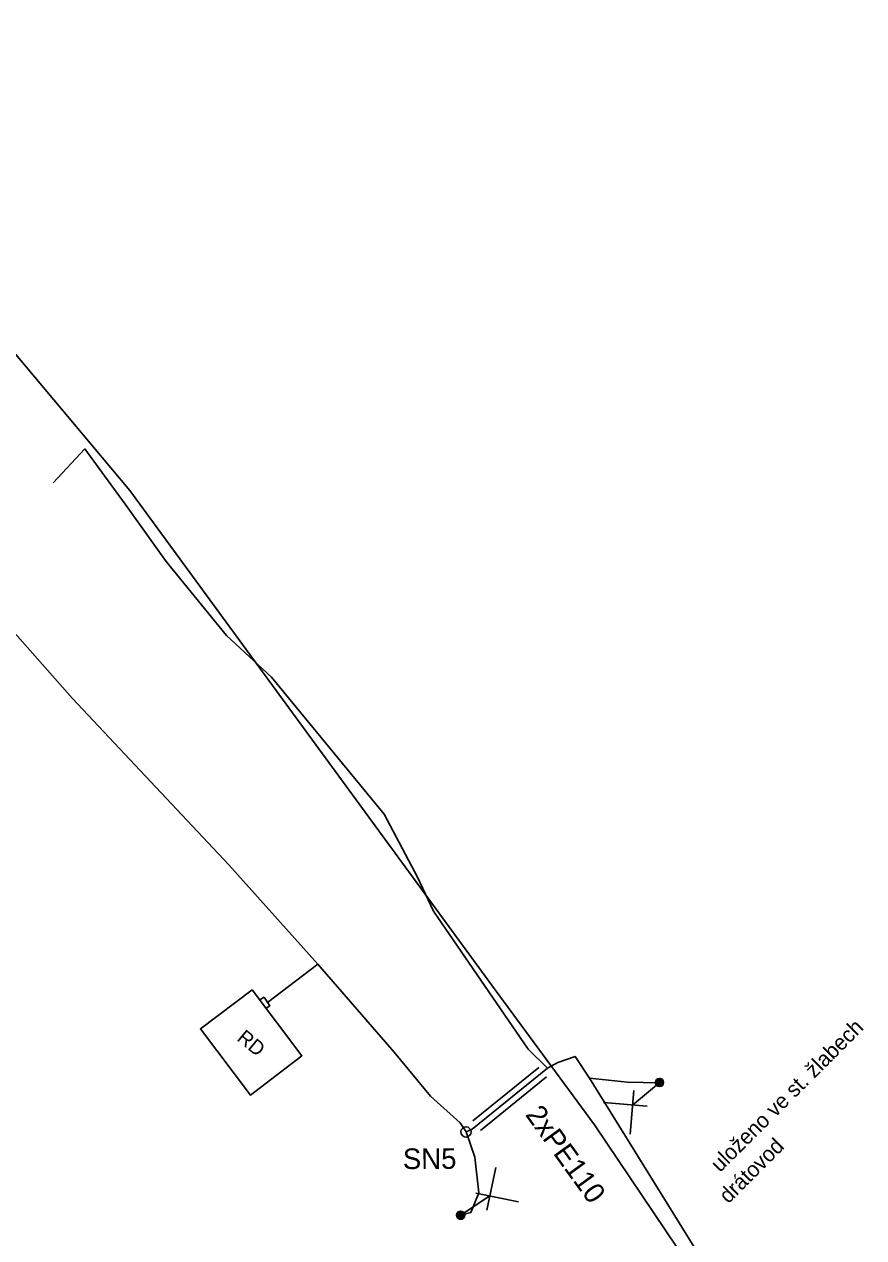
# Model space of a CAD drawing. Extents: x -731967 to -723173, y -945358 to -941505.
# Drawn here: x -725876.3 to -725835.6, y -942340.7 to -942281.8 of the extents above; entities that cross this region are included whole.
import ezdxf

# ---------------------------------------------------------------- set-up
doc = ezdxf.new("R2010")
doc.units = 0
for name, color, linetype in [('Vrstva 2', 7, 'Continuous'), ('Vrstva 28', 7, 'Continuous'), ('Vrstva 35', 7, 'Continuous')]:
    doc.layers.add(name, color=color, linetype=linetype)

msp = doc.modelspace()

# ---------------------------------------------------------------- linework, layer by layer
at = {"layer": 'Vrstva 2'}
for p, q in [((-725845.654, -942333.308), (-725846.804, -942334.272)), ((-725845.654, -942333.308), (-725846.804, -942334.272)), ((-725846.741, -942333.568), (-725846.928, -942335.682)), ((-725846.741, -942333.568), (-725846.928, -942335.682)), ((-725846.101, -942334.334), (-725848.213, -942334.147)), ((-725846.101, -942334.334), (-725848.213, -942334.147)), ((-725853.873, -942339.378), (-725853.443, -942337.3)), ((-725853.873, -942339.378), (-725853.443, -942337.3)), ((-725854.421, -942338.544), (-725852.344, -942338.974)), ((-725854.421, -942338.544), (-725852.344, -942338.974)), ((-725854.983, -942339.51), (-725853.728, -942338.686)), ((-725854.983, -942339.51), (-725853.728, -942338.686))]:
    msp.add_line(p, q, dxfattribs=at)
for points in [[(-725865.27, -942328.68), (-725862.85, -942331.88), (-725865.35, -942333.79), (-725867.779, -942330.578), (-725865.27, -942328.68)], [(-725865.27, -942328.68), (-725862.85, -942331.88), (-725865.35, -942333.79), (-725867.779, -942330.578), (-725865.27, -942328.68)], [(-725864.69, -942329.03), (-725864.901, -942329.168)], [(-725864.69, -942329.03), (-725864.901, -942329.168)], [(-725864.69, -942329.03), (-725864.41, -942329.46), (-725864.591, -942329.578)], [(-725864.69, -942329.03), (-725864.41, -942329.46), (-725864.591, -942329.578)], [(-725851.362, -942332.444), (-725854.56, -942335.039)], [(-725851.362, -942332.444), (-725854.56, -942335.039)], [(-725850.984, -942332.91), (-725854.182, -942335.505)], [(-725850.984, -942332.91), (-725854.182, -942335.505)], [(-725845.373, -942333.334), (-725845.315, -942333.243), (-725845.317, -942333.123), (-725845.384, -942333.029), (-725845.475, -942332.992), (-725845.585, -942333.01), (-725845.669, -942333.091), (-725845.692, -942333.19), (-725845.659, -942333.285), (-725845.57, -942333.354), (-725845.462, -942333.359), (-725845.382, -942333.315), (-725845.33, -942333.224), (-725845.34, -942333.115), (-725845.401, -942333.041), (-725845.488, -942333.011), (-725845.59, -942333.034), (-725845.657, -942333.109), (-725845.671, -942333.194), (-725845.635, -942333.284), (-725845.551, -942333.34), (-725845.46, -942333.339), (-725845.389, -942333.294), (-725845.347, -942333.207), (-725845.362, -942333.114), (-725845.416, -942333.056), (-725845.5, -942333.03), (-725845.59, -942333.058), (-725845.641, -942333.123), (-725845.651, -942333.201), (-725845.612, -942333.28), (-725845.537, -942333.323), (-725845.463, -942333.319), (-725845.396, -942333.274), (-725845.365, -942333.193), (-725845.381, -942333.118), (-725845.432, -942333.068), (-725845.512, -942333.05), (-725845.586, -942333.079), (-725845.624, -942333.134), (-725845.63, -942333.207), (-725845.591, -942333.275), (-725845.527, -942333.304), (-725845.464, -942333.298), (-725845.406, -942333.253), (-725845.385, -942333.184), (-725845.401, -942333.125), (-725845.45, -942333.08), (-725845.52, -942333.07), (-725845.577, -942333.098), (-725845.608, -942333.146), (-725845.608, -942333.212), (-725845.573, -942333.264), (-725845.522, -942333.286), (-725845.463, -942333.278), (-725845.417, -942333.235), (-725845.404, -942333.18), (-725845.419, -942333.131), (-725845.465, -942333.094), (-725845.523, -942333.09), (-725845.566, -942333.113), (-725845.591, -942333.158), (-725845.587, -942333.214), (-725845.557, -942333.252), (-725845.515, -942333.267), (-725845.465, -942333.256), (-725845.431, -942333.22), (-725845.424, -942333.178), (-725845.44, -942333.136), (-725845.479, -942333.11), (-725845.522, -942333.11), (-725845.553, -942333.129), (-725845.574, -942333.168), (-725845.567, -942333.21), (-725845.544, -942333.236), (-725845.507, -942333.248), (-725845.47, -942333.237), (-725845.448, -942333.208), (-725845.444, -942333.176), (-725845.46, -942333.145), (-725845.49, -942333.127), (-725845.519, -942333.13), (-725845.543, -942333.147), (-725845.555, -942333.176), (-725845.548, -942333.205), (-725845.53, -942333.222), (-725845.503, -942333.228), (-725845.477, -942333.218), (-725845.465, -942333.199), (-725845.464, -942333.177), (-725845.476, -942333.155), (-725845.496, -942333.145), (-725845.515, -942333.148), (-725845.53, -942333.161), (-725845.536, -942333.181), (-725845.529, -942333.196), (-725845.518, -942333.207), (-725845.501, -942333.209), (-725845.489, -942333.202), (-725845.482, -942333.191), (-725845.483, -942333.177)], [(-725845.373, -942333.334), (-725845.315, -942333.243), (-725845.317, -942333.123), (-725845.384, -942333.029), (-725845.475, -942332.992), (-725845.585, -942333.01), (-725845.669, -942333.091), (-725845.692, -942333.19), (-725845.659, -942333.285), (-725845.57, -942333.354), (-725845.462, -942333.359), (-725845.382, -942333.315), (-725845.33, -942333.224), (-725845.34, -942333.115), (-725845.401, -942333.041), (-725845.488, -942333.011), (-725845.59, -942333.034), (-725845.657, -942333.109), (-725845.671, -942333.194), (-725845.635, -942333.284), (-725845.551, -942333.34), (-725845.46, -942333.339), (-725845.389, -942333.294), (-725845.347, -942333.207), (-725845.362, -942333.114), (-725845.416, -942333.056), (-725845.5, -942333.03), (-725845.59, -942333.058), (-725845.641, -942333.123), (-725845.651, -942333.201), (-725845.612, -942333.28), (-725845.537, -942333.323), (-725845.463, -942333.319), (-725845.396, -942333.274), (-725845.365, -942333.193), (-725845.381, -942333.118), (-725845.432, -942333.068), (-725845.512, -942333.05), (-725845.586, -942333.079), (-725845.624, -942333.134), (-725845.63, -942333.207), (-725845.591, -942333.275), (-725845.527, -942333.304), (-725845.464, -942333.298), (-725845.406, -942333.253), (-725845.385, -942333.184), (-725845.401, -942333.125), (-725845.45, -942333.08), (-725845.52, -942333.07), (-725845.577, -942333.098), (-725845.608, -942333.146), (-725845.608, -942333.212), (-725845.573, -942333.264), (-725845.522, -942333.286), (-725845.463, -942333.278), (-725845.417, -942333.235), (-725845.404, -942333.18), (-725845.419, -942333.131), (-725845.465, -942333.094), (-725845.523, -942333.09), (-725845.566, -942333.113), (-725845.591, -942333.158), (-725845.587, -942333.214), (-725845.557, -942333.252), (-725845.515, -942333.267), (-725845.465, -942333.256), (-725845.431, -942333.22), (-725845.424, -942333.178), (-725845.44, -942333.136), (-725845.479, -942333.11), (-725845.522, -942333.11), (-725845.553, -942333.129), (-725845.574, -942333.168), (-725845.567, -942333.21), (-725845.544, -942333.236), (-725845.507, -942333.248), (-725845.47, -942333.237), (-725845.448, -942333.208), (-725845.444, -942333.176), (-725845.46, -942333.145), (-725845.49, -942333.127), (-725845.519, -942333.13), (-725845.543, -942333.147), (-725845.555, -942333.176), (-725845.548, -942333.205), (-725845.53, -942333.222), (-725845.503, -942333.228), (-725845.477, -942333.218), (-725845.465, -942333.199), (-725845.464, -942333.177), (-725845.476, -942333.155), (-725845.496, -942333.145), (-725845.515, -942333.148), (-725845.53, -942333.161), (-725845.536, -942333.181), (-725845.529, -942333.196), (-725845.518, -942333.207), (-725845.501, -942333.209), (-725845.489, -942333.202), (-725845.482, -942333.191), (-725845.483, -942333.177)], [(-725845.483, -942333.177), (-725845.491, -942333.169), (-725845.5, -942333.166), (-725845.51, -942333.168), (-725845.516, -942333.174), (-725845.517, -942333.182), (-725845.513, -942333.188), (-725845.508, -942333.19), (-725845.503, -942333.19), (-725845.5, -942333.186)], [(-725845.483, -942333.177), (-725845.491, -942333.169), (-725845.5, -942333.166), (-725845.51, -942333.168), (-725845.516, -942333.174), (-725845.517, -942333.182), (-725845.513, -942333.188), (-725845.508, -942333.19), (-725845.503, -942333.19), (-725845.5, -942333.186)], [(-725855.259, -942339.452), (-725855.327, -942339.536), (-725855.339, -942339.656), (-725855.283, -942339.757), (-725855.197, -942339.804), (-725855.086, -942339.799), (-725854.993, -942339.729), (-725854.959, -942339.632), (-725854.981, -942339.534), (-725855.062, -942339.455), (-725855.168, -942339.438), (-725855.253, -942339.472), (-725855.315, -942339.556), (-725855.317, -942339.665), (-725855.265, -942339.746), (-725855.183, -942339.787), (-725855.079, -942339.775), (-725855.002, -942339.708), (-725854.979, -942339.626), (-725855.005, -942339.532), (-725855.081, -942339.468), (-725855.172, -942339.457), (-725855.248, -942339.493), (-725855.299, -942339.575), (-725855.295, -942339.67), (-725855.249, -942339.734), (-725855.168, -942339.769), (-725855.076, -942339.752), (-725855.017, -942339.692), (-725854.998, -942339.617), (-725855.028, -942339.533), (-725855.098, -942339.482), (-725855.171, -942339.477), (-725855.243, -942339.515), (-725855.283, -942339.591), (-725855.276, -942339.668), (-725855.231, -942339.724), (-725855.154, -942339.751), (-725855.077, -942339.731), (-725855.033, -942339.68), (-725855.018, -942339.608), (-725855.05, -942339.536), (-725855.109, -942339.499), (-725855.173, -942339.499), (-725855.236, -942339.537), (-725855.265, -942339.602), (-725855.255, -942339.663), (-725855.212, -942339.714), (-725855.144, -942339.732), (-725855.084, -942339.711), (-725855.047, -942339.667), (-725855.04, -942339.601), (-725855.069, -942339.545), (-725855.117, -942339.518), (-725855.177, -942339.518), (-725855.227, -942339.555), (-725855.246, -942339.609), (-725855.236, -942339.66), (-725855.195, -942339.702), (-725855.139, -942339.712), (-725855.094, -942339.695), (-725855.063, -942339.652), (-725855.06, -942339.597), (-725855.086, -942339.555), (-725855.126, -942339.536), (-725855.177, -942339.541), (-725855.215, -942339.573), (-725855.226, -942339.613), (-725855.216, -942339.656), (-725855.18, -942339.687), (-725855.137, -942339.692), (-725855.104, -942339.676), (-725855.079, -942339.64), (-725855.081, -942339.598), (-725855.101, -942339.569), (-725855.135, -942339.553), (-725855.175, -942339.56), (-725855.2, -942339.586), (-725855.207, -942339.617), (-725855.194, -942339.65), (-725855.167, -942339.671), (-725855.138, -942339.672), (-725855.112, -942339.659), (-725855.096, -942339.631), (-725855.1, -942339.601), (-725855.115, -942339.582), (-725855.142, -942339.572), (-725855.169, -942339.579), (-725855.184, -942339.597), (-725855.187, -942339.619), (-725855.178, -942339.642), (-725855.159, -942339.654), (-725855.139, -942339.654), (-725855.124, -942339.642), (-725855.115, -942339.624), (-725855.12, -942339.607), (-725855.13, -942339.595), (-725855.146, -942339.59), (-725855.159, -942339.597), (-725855.167, -942339.607), (-725855.168, -942339.621)], [(-725855.259, -942339.452), (-725855.327, -942339.536), (-725855.339, -942339.656), (-725855.283, -942339.757), (-725855.197, -942339.804), (-725855.086, -942339.799), (-725854.993, -942339.729), (-725854.959, -942339.632), (-725854.981, -942339.534), (-725855.062, -942339.455), (-725855.168, -942339.438), (-725855.253, -942339.472), (-725855.315, -942339.556), (-725855.317, -942339.665), (-725855.265, -942339.746), (-725855.183, -942339.787), (-725855.079, -942339.775), (-725855.002, -942339.708), (-725854.979, -942339.626), (-725855.005, -942339.532), (-725855.081, -942339.468), (-725855.172, -942339.457), (-725855.248, -942339.493), (-725855.299, -942339.575), (-725855.295, -942339.67), (-725855.249, -942339.734), (-725855.168, -942339.769), (-725855.076, -942339.752), (-725855.017, -942339.692), (-725854.998, -942339.617), (-725855.028, -942339.533), (-725855.098, -942339.482), (-725855.171, -942339.477), (-725855.243, -942339.515), (-725855.283, -942339.591), (-725855.276, -942339.668), (-725855.231, -942339.724), (-725855.154, -942339.751), (-725855.077, -942339.731), (-725855.033, -942339.68), (-725855.018, -942339.608), (-725855.05, -942339.536), (-725855.109, -942339.499), (-725855.173, -942339.499), (-725855.236, -942339.537), (-725855.265, -942339.602), (-725855.255, -942339.663), (-725855.212, -942339.714), (-725855.144, -942339.732), (-725855.084, -942339.711), (-725855.047, -942339.667), (-725855.04, -942339.601), (-725855.069, -942339.545), (-725855.117, -942339.518), (-725855.177, -942339.518), (-725855.227, -942339.555), (-725855.246, -942339.609), (-725855.236, -942339.66), (-725855.195, -942339.702), (-725855.139, -942339.712), (-725855.094, -942339.695), (-725855.063, -942339.652), (-725855.06, -942339.597), (-725855.086, -942339.555), (-725855.126, -942339.536), (-725855.177, -942339.541), (-725855.215, -942339.573), (-725855.226, -942339.613), (-725855.216, -942339.656), (-725855.18, -942339.687), (-725855.137, -942339.692), (-725855.104, -942339.676), (-725855.079, -942339.64), (-725855.081, -942339.598), (-725855.101, -942339.569), (-725855.135, -942339.553), (-725855.175, -942339.56), (-725855.2, -942339.586), (-725855.207, -942339.617), (-725855.194, -942339.65), (-725855.167, -942339.671), (-725855.138, -942339.672), (-725855.112, -942339.659), (-725855.096, -942339.631), (-725855.1, -942339.601), (-725855.115, -942339.582), (-725855.142, -942339.572), (-725855.169, -942339.579), (-725855.184, -942339.597), (-725855.187, -942339.619), (-725855.178, -942339.642), (-725855.159, -942339.654), (-725855.139, -942339.654), (-725855.124, -942339.642), (-725855.115, -942339.624), (-725855.12, -942339.607), (-725855.13, -942339.595), (-725855.146, -942339.59), (-725855.159, -942339.597), (-725855.167, -942339.607), (-725855.168, -942339.621)], [(-725855.168, -942339.621), (-725855.161, -942339.63), (-725855.152, -942339.634), (-725855.142, -942339.633), (-725855.136, -942339.628), (-725855.134, -942339.619), (-725855.137, -942339.613), (-725855.142, -942339.611), (-725855.147, -942339.61), (-725855.15, -942339.614)], [(-725855.168, -942339.621), (-725855.161, -942339.63), (-725855.152, -942339.634), (-725855.142, -942339.633), (-725855.136, -942339.628), (-725855.134, -942339.619), (-725855.137, -942339.613), (-725855.142, -942339.611), (-725855.147, -942339.61), (-725855.15, -942339.614)]]:
    msp.add_lwpolyline(points, dxfattribs=at)
for centre, radius in [((-725845.501, -942333.18), 0.2), ((-725845.501, -942333.18), 0.2), ((-725854.89, -942335.58), 0.25), ((-725854.89, -942335.58), 0.25), ((-725855.15, -942339.62), 0.2), ((-725855.15, -942339.62), 0.2)]:
    msp.add_circle(centre, radius, dxfattribs=at)
at = {"layer": 'Vrstva 28'}
for points in [[(-725862.08, -942327.44), (-725866.4, -942322.61), (-725873.98, -942314.54), (-725876.66, -942311.52), (-725885.15, -942302.9), (-725886.71, -942301.62), (-725889.6, -942298.75), (-725896.94, -942291.72), (-725897.69, -942290.94), (-725907.13, -942281.91), (-725914.38, -942274.9), (-725919.89, -942269.38), (-725917.57, -942266.37), (-725917.3, -942265.77), (-725917.82, -942264.96), (-725926.95, -942256.88), (-725934.67, -942250.17), (-725946.58, -942239.58)], [(-725862.08, -942327.44), (-725866.4, -942322.61), (-725873.98, -942314.54), (-725876.66, -942311.52), (-725885.15, -942302.9), (-725886.71, -942301.62), (-725889.6, -942298.75), (-725896.94, -942291.72), (-725897.69, -942290.94), (-725907.13, -942281.91), (-725914.38, -942274.9), (-725919.89, -942269.38), (-725917.57, -942266.37), (-725917.3, -942265.77), (-725917.82, -942264.96), (-725926.95, -942256.88), (-725934.67, -942250.17), (-725946.58, -942239.58)], [(-725848.9, -942332.97), (-725849.6, -942331.91), (-725850.43, -942332.2), (-725850.93, -942332.48), (-725851.88, -942331.56), (-725856.47, -942324.86), (-725857.24, -942323.21), (-725858.86, -942320.15), (-725864.33, -942313.5), (-725866.51, -942311.48), (-725869.44, -942307.89), (-725871.3, -942305.28), (-725873.39, -942302.42), (-725874.93, -942304.07)], [(-725848.9, -942332.97), (-725849.6, -942331.91), (-725850.43, -942332.2), (-725850.93, -942332.48), (-725851.88, -942331.56), (-725856.47, -942324.86), (-725857.24, -942323.21), (-725858.86, -942320.15), (-725864.33, -942313.5), (-725866.51, -942311.48), (-725869.44, -942307.89), (-725871.3, -942305.28), (-725873.39, -942302.42), (-725874.93, -942304.07)], [(-725854.89, -942335.58), (-725855.17, -942335.13), (-725856.62, -942333.84), (-725858.37, -942331.7), (-725862.08, -942327.44), (-725864.52, -942329.3)], [(-725854.89, -942335.58), (-725855.17, -942335.13), (-725856.62, -942333.84), (-725858.37, -942331.7), (-725862.08, -942327.44), (-725864.52, -942329.3)], [(-725850.93, -942332.48), (-725854.59, -942335.45), (-725854.89, -942335.58), (-725854.46, -942336.8), (-725854.27, -942338.53), (-725854.65, -942339.49), (-725855.15, -942339.62)], [(-725850.93, -942332.48), (-725854.59, -942335.45), (-725854.89, -942335.58), (-725854.46, -942336.8), (-725854.27, -942338.53), (-725854.65, -942339.49), (-725855.15, -942339.62)], [(-725841.11, -942345.53), (-725848.9, -942332.97), (-725847.06, -942333.17), (-725845.53, -942333.2)], [(-725841.11, -942345.53), (-725848.9, -942332.97), (-725847.06, -942333.17), (-725845.53, -942333.2)]]:
    msp.add_lwpolyline(points, dxfattribs=at)
at = {"layer": 'Vrstva 35'}
for p, q in [((-725903.865, -942265.52), (-725871.203, -942304.447)), ((-725871.203, -942304.447), (-725853.474, -942328.679)), ((-725853.474, -942328.679), (-725848.655, -942335.231)), ((-725848.655, -942335.231), (-725842.27, -942344.701))]:
    msp.add_line(p, q, dxfattribs=at)

# ---------------------------------------------------------------- texts
at = {"layer": 'Vrstva 2'}
for s, height, rotation, p in [('uloženo ve st. žlabech', 0.74999, 44.94577, (-725842.569, -942337.574)), ('RD', 0.7, 320.52768, (-725866.049, -942331.101)), ('RD', 0.7, 320.52768, (-725866.049, -942331.101)), ('2xPE110', 1, 305.89738, (-725852.042, -942334.744)), ('drátovod', 0.75, 44.94577, (-725842.161, -942339.092)), ('SN5', 1, 0.26931, (-725857.952, -942337.381)), ('SN5', 1, 0.26931, (-725857.952, -942337.381))]:
    msp.add_text(s, height=height, rotation=rotation, dxfattribs=at).set_placement(p)

doc.saveas('drawing.dxf')
